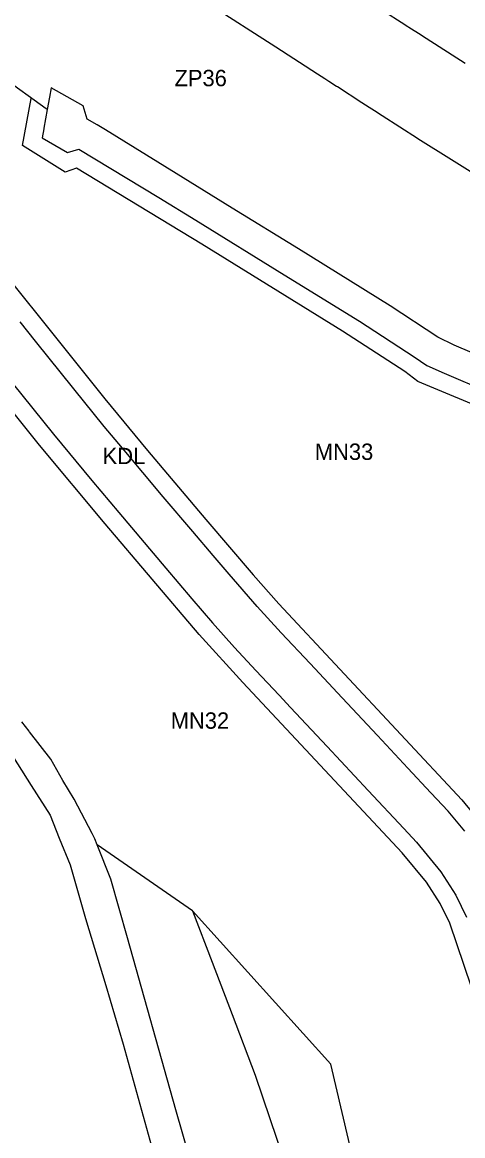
# Model space of a CAD drawing. Extents: x 7428080 to 7432143, y 5545880 to 5549217.
# Drawn here: x 7430737.9 to 7430887.1, y 5546851.1 to 5547228.4 of the extents above; entities that cross this region are included whole.
import ezdxf

# ---------------------------------------------------------------- set-up
doc = ezdxf.new("R2010")
doc.units = 0
for name, color, linetype in [('CZ_L_linie rozgraniczające tereny o różnym przeznaczeniu oraz różnych warunkach ich zabudowy i zagospodarowania', 7, 'Continuous'), ('CZ_L_maksymalne nieprzekraczalne linie zabudowy', 7, 'Continuous'), ('CZ_L_opisy_linie rozgraniczające tereny o różnym przeznaczeniu oraz różnych warunkach ich zabudowy i zagospodarowania', 7, 'Continuous')]:
    doc.layers.add(name, color=color, linetype=linetype)

msp = doc.modelspace()

# ---------------------------------------------------------------- linework, layer by layer
at = {"layer": 'CZ_L_linie rozgraniczające tereny o różnym przeznaczeniu oraz różnych warunkach ich zabudowy i zagospodarowania'}
for p, q in [((7430800.88, 5547234.82), (7430823.75, 5547220.06)), ((7430867.45, 5547227.54), (7430859.68, 5547232.57)), ((7430867.63, 5547227.45), (7430867.45, 5547227.54)), ((7430869.71, 5547226.11), (7430867.63, 5547227.45)), ((7430872.05, 5547224.6), (7430869.71, 5547226.11)), ((7430874.73, 5547222.87), (7430872.05, 5547224.6)), ((7430823.75, 5547220.06), (7430837.9, 5547210.93)), ((7430887.88, 5547214.39), (7430874.73, 5547222.87)), ((7430746.02, 5547199.03), (7430731, 5547209.91)), ((7430837.9, 5547210.93), (7430840.41, 5547209.31)), ((7430840.41, 5547209.31), (7430841.77, 5547208.43)), ((7430747.68, 5547206.25), (7430747.1, 5547203.09)), ((7430758.49, 5547200.14), (7430747.68, 5547206.25)), ((7430841.77, 5547208.43), (7430844.33, 5547206.78)), ((7430844.33, 5547206.78), (7430844.61, 5547206.6)), ((7430844.61, 5547206.6), (7430852.92, 5547201.24)), ((7430747.1, 5547203.09), (7430746.33, 5547198.84)), ((7430852.92, 5547201.24), (7430855.33, 5547199.69)), ((7430746.33, 5547198.84), (7430745.17, 5547192.5)), ((7430746.33, 5547198.84), (7430746.02, 5547199.03)), ((7430759.83, 5547195.63), (7430758.49, 5547200.14)), ((7430855.33, 5547199.69), (7430857.2, 5547198.48)), ((7430857.2, 5547198.48), (7430859.79, 5547196.81)), ((7430763.28, 5547193.61), (7430759.83, 5547195.63)), ((7430859.79, 5547196.81), (7430871.72, 5547189.11)), ((7430745.14, 5547192.31), (7430744.58, 5547189.25)), ((7430745.17, 5547192.5), (7430745.14, 5547192.31)), ((7430766.08, 5547191.97), (7430763.28, 5547193.61)), ((7430789.97, 5547177.22), (7430766.08, 5547191.97)), ((7430744.58, 5547189.25), (7430753.2, 5547184.33)), ((7430871.72, 5547189.11), (7430871.81, 5547189.07)), ((7430871.81, 5547189.07), (7430871.92, 5547188.98)), ((7430871.92, 5547188.98), (7430905.11, 5547168.32)), ((7430753.2, 5547184.33), (7430756.99, 5547185.38)), ((7430756.99, 5547185.38), (7430784.11, 5547169.08)), ((7430809.03, 5547165.46), (7430789.97, 5547177.22)), ((7430784.11, 5547169.08), (7430796.67, 5547161.33)), ((7430831.43, 5547151.64), (7430809.03, 5547165.46)), ((7430796.67, 5547161.33), (7430826.57, 5547142.88)), ((7430831.45, 5547151.62), (7430831.43, 5547151.64)), ((7430862.45, 5547132.35), (7430831.45, 5547151.62)), ((7430826.57, 5547142.88), (7430852.12, 5547127.12)), ((7430878.66, 5547121.72), (7430862.45, 5547132.35)), ((7430742.39, 5547120.33), (7430737.11, 5547126.94)), ((7430852.12, 5547127.12), (7430852.12, 5547127.12)), ((7430852.12, 5547127.12), (7430870.57, 5547115.07)), ((7430755.36, 5547104.18), (7430742.39, 5547120.33)), ((7430884.23, 5547118.97), (7430878.66, 5547121.72)), ((7430897.8, 5547113.13), (7430884.23, 5547118.97)), ((7430870.57, 5547115.07), (7430870.58, 5547115.06)), ((7430870.58, 5547115.06), (7430874.94, 5547112.08)), ((7430874.94, 5547112.08), (7430880.83, 5547109.55)), ((7430880.83, 5547109.55), (7430896.03, 5547103)), ((7430734.48, 5547106.2), (7430748.41, 5547088.89)), ((7430765.63, 5547091.44), (7430755.36, 5547104.18)), ((7430748.41, 5547088.89), (7430761.41, 5547073.16)), ((7430771.84, 5547084.06), (7430765.63, 5547091.44)), ((7430785.65, 5547067.65), (7430771.84, 5547084.06)), ((7430761.41, 5547073.16), (7430770.57, 5547062.27)), ((7430795.62, 5547055.85), (7430785.65, 5547067.65)), ((7430770.57, 5547062.27), (7430786.45, 5547043.49)), ((7430802.54, 5547047.73), (7430795.62, 5547055.85)), ((7430807.92, 5547041.42), (7430802.54, 5547047.73)), ((7430786.45, 5547043.49), (7430795.33, 5547033.06)), ((7430817.47, 5547030.46), (7430807.92, 5547041.42)), ((7430795.33, 5547033.06), (7430802.26, 5547024.93)), ((7430825.57, 5547021.58), (7430817.47, 5547030.46)), ((7430802.26, 5547024.93), (7430809.81, 5547016.6)), ((7430835.37, 5547011.1), (7430825.57, 5547021.58)), ((7430809.81, 5547016.6), (7430817, 5547008.77)), ((7430817, 5547008.77), (7430824.84, 5547000.4)), ((7430846.18, 5546999.55), (7430835.37, 5547011.1)), ((7430824.84, 5547000.4), (7430828.7, 5546996.28)), ((7430858.16, 5546986.76), (7430846.18, 5546999.55)), ((7430828.7, 5546996.28), (7430841.12, 5546983.01)), ((7430740.2, 5546988.17), (7430737.75, 5546991.41)), ((7430740.32, 5546988), (7430740.2, 5546988.17)), ((7430747.5, 5546978.76), (7430740.32, 5546988)), ((7430868.53, 5546975.68), (7430858.16, 5546986.76)), ((7430841.12, 5546983.01), (7430855.02, 5546968.16)), ((7430732.96, 5546982.28), (7430740.94, 5546969.76)), ((7430751.66, 5546971.49), (7430747.5, 5546978.76)), ((7430876.32, 5546967.36), (7430868.53, 5546975.68)), ((7430755.42, 5546965.12), (7430751.66, 5546971.49)), ((7430740.94, 5546969.76), (7430747.29, 5546959.8)), ((7430855.02, 5546968.16), (7430867.16, 5546955.2)), ((7430882.17, 5546961.12), (7430876.32, 5546967.36)), ((7430761.52, 5546953.52), (7430755.42, 5546965.12)), ((7430747.29, 5546959.8), (7430750.33, 5546951.99)), ((7430887.76, 5546954.35), (7430882.17, 5546961.12)), ((7430762.46, 5546951.72), (7430761.52, 5546953.52)), ((7430867.16, 5546955.2), (7430871.41, 5546950.61)), ((7430750.33, 5546951.99), (7430754.07, 5546942.89)), ((7430763.23, 5546949.69), (7430762.46, 5546951.72)), ((7430767.85, 5546938.02), (7430763.23, 5546949.69)), ((7430795.56, 5546927.38), (7430763.23, 5546949.69)), ((7430871.41, 5546950.61), (7430879.68, 5546940.57)), ((7430754.07, 5546942.89), (7430759.25, 5546924.71)), ((7430773.56, 5546918.18), (7430767.85, 5546938.02)), ((7430879.68, 5546940.57), (7430884.75, 5546932.69)), ((7430884.75, 5546932.69), (7430888.34, 5546925.21)), ((7430842.37, 5546875.38), (7430795.56, 5546927.38)), ((7430795.56, 5546927.38), (7430802.17, 5546909.98)), ((7430759.25, 5546924.71), (7430766.13, 5546902.04)), ((7430789.89, 5546859.94), (7430773.56, 5546918.18)), ((7430802.17, 5546909.98), (7430808.92, 5546892.22)), ((7430766.13, 5546902.04), (7430772.09, 5546882.16)), ((7430808.92, 5546892.22), (7430816.73, 5546871.65)), ((7430772.09, 5546882.16), (7430782.77, 5546843.47)), ((7430871.63, 5546751.13), (7430842.37, 5546875.38)), ((7430816.73, 5546871.65), (7430835.13, 5546817.59)), ((7430799.48, 5546826.52), (7430789.89, 5546859.94))]:
    msp.add_line(p, q, dxfattribs=at)
at = {"layer": 'CZ_L_maksymalne nieprzekraczalne linie zabudowy'}
for points in [[(7430654.54, 5547240.29), (7430665.61, 5547225.73), (7430675.78, 5547211.67), (7430680.29, 5547205.95), (7430715.45, 5547163.65), (7430765.79, 5547100.82), (7430780.35, 5547083.28), (7430800.05, 5547059.92), (7430816.12, 5547041.16), (7430824.8, 5547031.35), (7430886.76, 5546964.98), (7430896.64, 5546952.97), (7430901.69, 5546945.24), (7430901.95, 5546945.2), (7430902.39, 5546945.93), (7430903.3, 5546948.81), (7430911.71, 5546982.58), (7430913.18, 5546988.55), (7430923.67, 5547028.55), (7430938.24, 5547068.96)], [(7430937.82, 5547069.44), (7430930.19, 5547072.87), (7430898.18, 5547095.68), (7430871.92, 5547106.73), (7430867.46, 5547110.07), (7430846.33, 5547123.74), (7430798.67, 5547153.17), (7430756.26, 5547179.01), (7430752.36, 5547177.58), (7430738, 5547186.63), (7430740.91, 5547202.6)], [(7431001.77, 5546688.14), (7430985.61, 5546730.31), (7430971.26, 5546768.92), (7430965.85, 5546780.6), (7430952.8, 5546802.25), (7430945.6, 5546813.48), (7430915, 5546852.27), (7430908.72, 5546860.69), (7430907, 5546862.78), (7430903.21, 5546869.02), (7430898.44, 5546877.88), (7430897.33, 5546880.63), (7430894.86, 5546887.15), (7430882.68, 5546923.15), (7430879.42, 5546929.87), (7430874.82, 5546937.03), (7430866.55, 5546947.03), (7430812.62, 5547004.67), (7430797.81, 5547020.91), (7430765.98, 5547058.41), (7430743.74, 5547085.12), (7430692.31, 5547149.26)]]:
    msp.add_lwpolyline(points, dxfattribs=at)

# ---------------------------------------------------------------- texts
at = {"layer": 'CZ_L_opisy_linie rozgraniczające tereny o różnym przeznaczeniu oraz różnych warunkach ich zabudowy i zagospodarowania'}
for s, p in [('ZP36', (7430789.44, 5547206.74)), ('KDL', (7430765.1, 5547078.69)), ('MN33', (7430836.99, 5547080.12)), ('MN32', (7430788.16, 5546989.03))]:
    msp.add_text(s, height=5.549, dxfattribs=at).set_placement(p)

doc.saveas('drawing.dxf')
